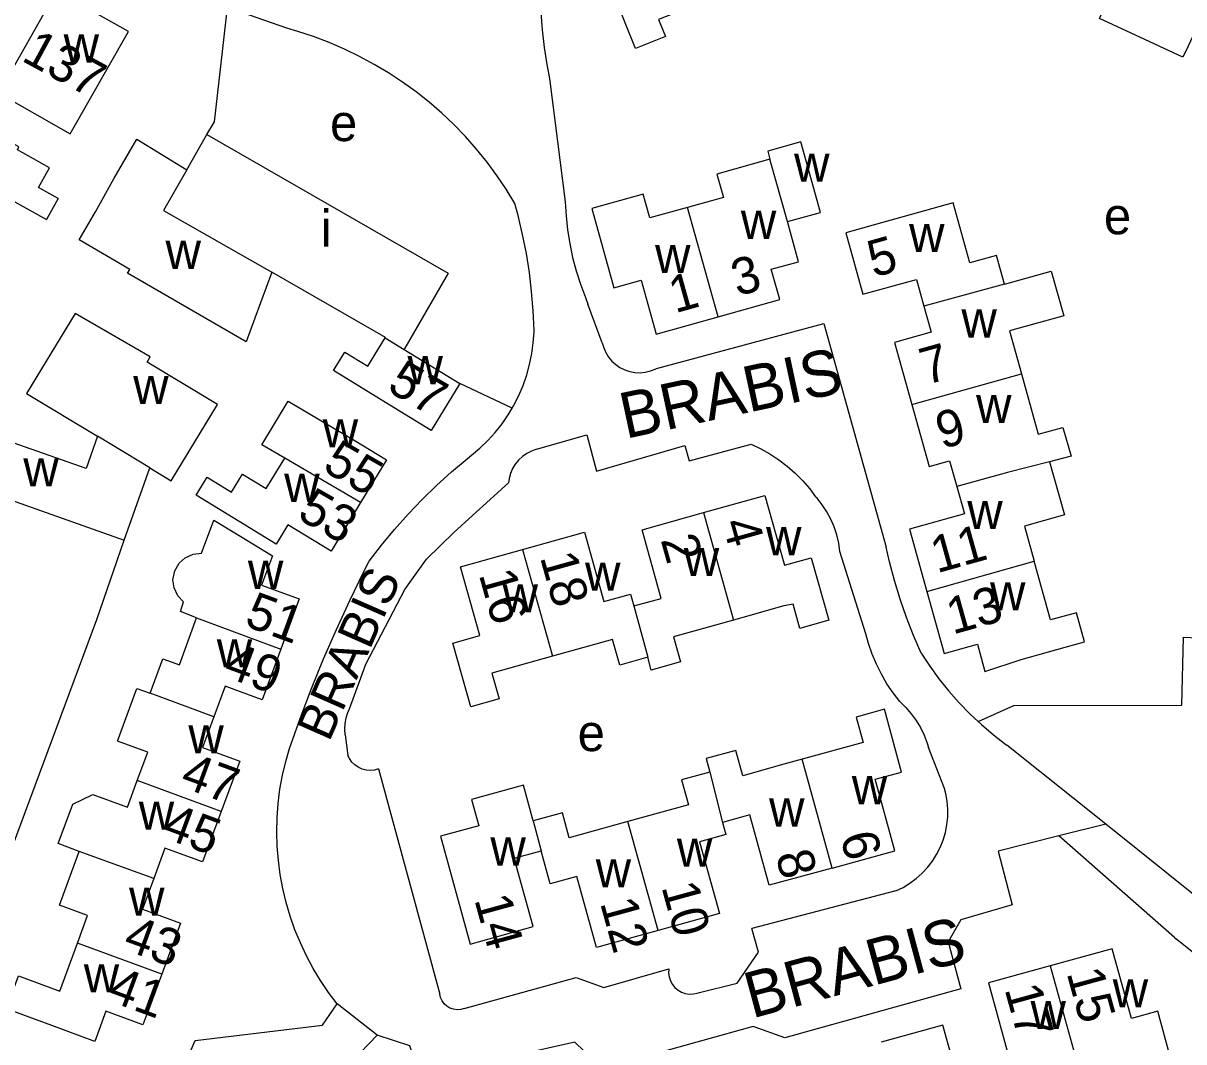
# Model space of a CAD drawing. Extents: x 162883 to 165538, y 383986 to 385172.
# Drawn here: x 164417 to 164543.6, y 384633.2 to 384744.4 of the extents above; entities that cross this region are included whole.
import ezdxf

# ---------------------------------------------------------------- set-up
doc = ezdxf.new("R2010")
doc.units = 0
for name, color, linetype in [('BLT_Basislijn', 7, 'Continuous'), ('BLT_Bebouwing', 7, 'Continuous'), ('BLT_Centroide', 7, 'Continuous'), ('BLT_Huisnummer', 7, 'Continuous'), ('BLT_Huisnummer_ tussenligend', 7, 'Continuous'), ('BLT_Onderverdeling_panden', 7, 'Continuous'), ('BLT_Straatnaam', 7, 'Continuous'), ('BLT_Straatnaam_verkleind', 7, 'Continuous')]:
    doc.layers.add(name, color=color, linetype=linetype)

msp = doc.modelspace()

# ---------------------------------------------------------------- linework, layer by layer
at = {"layer": 'BLT_Basislijn'}
for p, q in [((164445.76, 384743.83), (164439.29, 384746.09)), ((164474.44, 384738.33), (164476.15, 384724.88)), ((164480.19, 384709.5), (164478.6, 384713.69)), ((164470.36, 384702.37), (164464.66, 384705.05)), ((164473.02, 384697.86), (164478.51, 384699.46)), ((164508.96, 384677.72), (164506.12, 384686.72)), ((164452.15, 384666.7), (164452.43, 384664.43)), ((164517.53, 384660.85), (164515.78, 384665.3)), ((164535.12, 384656.94), (164524.34, 384665.57)), ((164455.77, 384662.98), (164462.47, 384638.39)), ((164535.12, 384656.94), (164530.02, 384655.67)), ((164545.44, 384648.68), (164535.12, 384656.94)), ((164542.62, 384644.56), (164530.02, 384655.67)), ((164512.23, 384649.67), (164496.52, 384645.57)), ((164490.78, 384638.57), (164494.89, 384639.58)), ((164455.61, 384633.93), (164451.25, 384637.34))]:
    msp.add_line(p, q, dxfattribs=at)
for points in [[(164437.05, 384732.24), (164437.89, 384733.59), (164439.29, 384746.09)], [(164473.5, 384745.53), (164473.64, 384743.63), (164473.85, 384741.73), (164474.15, 384739.85), (164474.44, 384738.33)], [(164470.66, 384724.69), (164469.71, 384726.24), (164468.69, 384727.75), (164467.61, 384729.22), (164466.46, 384730.63), (164465.26, 384731.99), (164463.99, 384733.3), (164462.67, 384734.55), (164461.29, 384735.75), (164459.87, 384736.88), (164458.39, 384737.95), (164456.87, 384738.95), (164455.31, 384739.88), (164453.7, 384740.75), (164452.07, 384741.54), (164450.39, 384742.26), (164448.69, 384742.91), (164446.96, 384743.48), (164445.76, 384743.83)], [(164472.74, 384710.86), (164472.65, 384712.96), (164472.48, 384715.07), (164472.23, 384717.16), (164471.91, 384719.25), (164471.5, 384721.32), (164471.01, 384723.37), (164470.66, 384724.69)], [(164476.15, 384724.88), (164476.23, 384723.35), (164476.39, 384721.82), (164476.63, 384720.31), (164476.95, 384718.81), (164477.35, 384717.33), (164477.83, 384715.87), (164478.37, 384714.44), (164478.6, 384713.69)], [(164486.09, 384706.68), (164504.36, 384711.61), (164511.18, 384687.17)], [(164470.36, 384702.37), (164470.54, 384702.67), (164471.08, 384703.74), (164471.55, 384704.84), (164471.94, 384705.98), (164472.26, 384707.13), (164472.5, 384708.31), (164472.66, 384709.49), (164472.74, 384710.69), (164472.74, 384710.86)], [(164480.19, 384709.5), (164480.34, 384708.95), (164480.57, 384708.42), (164480.87, 384707.93), (164481.23, 384707.49), (164481.65, 384707.11), (164482.12, 384706.78), (164482.64, 384706.53), (164483.18, 384706.35), (164483.74, 384706.25), (164484.31, 384706.22), (164484.88, 384706.28), (164485.44, 384706.41), (164485.97, 384706.62), (164486.09, 384706.68)], [(164465.93, 384697.21), (164466.84, 384697.99), (164467.7, 384698.82), (164468.51, 384699.71), (164469.25, 384700.65), (164469.93, 384701.64), (164470.36, 384702.37)], [(164478.51, 384699.46), (164479.57, 384695.46), (164489.18, 384698.26), (164489.66, 384696.61), (164496.44, 384698.42)], [(164473.02, 384697.86), (164472.47, 384697.67), (164471.96, 384697.41), (164471.48, 384697.08), (164471.06, 384696.69), (164470.69, 384696.24), (164470.39, 384695.75), (164470.16, 384695.22), (164470.01, 384694.67), (164469.94, 384694.2)], [(164496.44, 384698.42), (164497.49, 384697.93), (164498.49, 384697.36), (164499.46, 384696.72), (164500.38, 384696.02), (164501.25, 384695.25), (164502.06, 384694.43), (164502.82, 384693.55), (164503.47, 384692.69)], [(164454.75, 384685.65), (164456.1, 384687.41), (164457.52, 384689.12), (164458.99, 384690.77), (164460.52, 384692.37), (164462.11, 384693.92), (164463.75, 384695.4), (164465.45, 384696.83), (164465.93, 384697.21)], [(164452.62, 384669.54), (164454.37, 384674.4), (164458.63, 384682.55), (164461, 384685.87), (164464.03, 384688.8), (164469.94, 384694.2)], [(164506.12, 384686.72), (164505.99, 384687.62), (164505.78, 384688.52), (164505.49, 384689.39), (164505.13, 384690.23), (164504.69, 384691.03), (164504.19, 384691.8), (164503.62, 384692.52), (164503.47, 384692.69)], [(164408.67, 384626.64), (164409.63, 384627.68), (164410.94, 384641.5), (164425.03, 384679.28), (164428.03, 384687.96)], [(164514.97, 384675.61), (164514.14, 384677.55), (164513.37, 384679.52), (164512.68, 384681.52), (164512.07, 384683.54), (164511.54, 384685.58), (164511.18, 384687.17)], [(164446.04, 384665.19), (164447.21, 384668.49), (164448.46, 384671.75), (164449.78, 384674.99), (164451.17, 384678.2), (164452.63, 384681.37), (164454.17, 384684.51), (164454.75, 384685.65)], [(164512.65, 384670.33), (164511.92, 384671.28), (164511.24, 384672.28), (164510.64, 384673.32), (164510.1, 384674.4), (164509.64, 384675.51), (164509.25, 384676.65), (164508.96, 384677.72)], [(164521.22, 384668.14), (164525.08, 384669.9), (164543.44, 384669.93), (164543.63, 384677.35), (164554, 384676.9)], [(164514.97, 384675.61), (164515.92, 384674.19), (164516.93, 384672.81), (164518, 384671.48), (164519.13, 384670.2), (164520.32, 384668.97), (164521.22, 384668.14)], [(164512.65, 384670.33), (164513.31, 384669.69), (164513.91, 384669), (164514.44, 384668.26), (164514.91, 384667.48), (164515.31, 384666.66), (164515.63, 384665.8), (164515.78, 384665.3)], [(164452.15, 384666.7), (164452.1, 384667.32), (164452.13, 384667.94), (164452.25, 384668.55), (164452.44, 384669.14), (164452.62, 384669.54)], [(164521.22, 384668.14), (164521.57, 384667.81), (164522.87, 384666.7), (164524.23, 384665.65), (164524.34, 384665.57)], [(164451.25, 384637.34), (164450.31, 384638.58), (164449.44, 384639.87), (164448.64, 384641.2), (164447.9, 384642.58), (164447.24, 384643.99), (164446.65, 384645.43), (164446.14, 384646.9), (164445.7, 384648.39), (164445.33, 384649.91), (164445.05, 384651.44), (164444.85, 384652.98), (164444.72, 384654.54), (164444.68, 384656.09), (164444.71, 384657.65), (164444.83, 384659.2), (164445.02, 384660.75), (164445.3, 384662.28), (164445.65, 384663.8), (164446.04, 384665.19)], [(164455.77, 384662.98), (164455.33, 384662.85), (164454.88, 384662.81), (164454.42, 384662.85), (164453.98, 384662.96), (164453.56, 384663.15), (164453.18, 384663.41), (164452.86, 384663.73), (164452.59, 384664.11), (164452.43, 384664.43)], [(164512.23, 384649.67), (164513.01, 384650.04), (164513.75, 384650.49), (164514.44, 384651), (164515.09, 384651.58), (164515.68, 384652.21), (164516.21, 384652.89), (164516.67, 384653.62), (164517.06, 384654.39), (164517.38, 384655.19), (164517.63, 384656.02), (164517.8, 384656.87), (164517.88, 384657.73), (164517.89, 384658.59), (164517.82, 384659.45), (164517.67, 384660.3), (164517.53, 384660.85)], [(164530.02, 384655.67), (164523.39, 384654.01), (164524.91, 384648.14), (164519.33, 384646.51), (164517.95, 384644.09), (164519.33, 384638.96), (164500.12, 384633.64), (164496.67, 384634.86), (164480.18, 384630.26), (164477.19, 384633.17), (164460.34, 384629.38), (164459.19, 384632.74), (164455.61, 384633.93)], [(164494.89, 384639.58), (164497.22, 384642.99), (164496.52, 384645.57)], [(164542.62, 384644.56), (164543.62, 384643.83), (164544.57, 384643.03), (164545.47, 384642.18), (164546.31, 384641.27), (164547.09, 384640.3), (164547.8, 384639.29), (164548.45, 384638.24), (164549.03, 384637.15), (164549.54, 384636.02), (164549.97, 384634.86), (164550.33, 384633.67), (164550.49, 384633.01)], [(164465.12, 384636.82), (164477.35, 384640.22), (164480.35, 384639.11), (164487.45, 384641.14)], [(164487.45, 384641.14), (164487.43, 384640.7), (164487.49, 384640.27), (164487.63, 384639.85), (164487.84, 384639.46), (164488.12, 384639.12), (164488.46, 384638.84), (164488.84, 384638.62), (164489.25, 384638.47), (164489.69, 384638.4), (164490.13, 384638.41), (164490.56, 384638.5), (164490.78, 384638.57)], [(164465.12, 384636.82), (164464.74, 384636.71), (164464.34, 384636.69), (164463.95, 384636.74), (164463.57, 384636.88), (164463.23, 384637.09), (164462.94, 384637.35), (164462.71, 384637.68), (164462.55, 384638.04), (164462.47, 384638.39)], [(164455.61, 384633.93), (164446.71, 384624.64), (164445.93, 384620.98), (164443.27, 384620.28), (164440.41, 384622.61), (164447.71, 384630.68), (164446.66, 384632.04), (164441.79, 384631.37), (164436.24, 384626.66), (164433.96, 384629.09), (164435.76, 384633.33), (164449.67, 384635.02), (164451.25, 384637.34)]]:
    msp.add_lwpolyline(points, dxfattribs=at)
at = {"layer": 'BLT_Bebouwing'}
for p, q in [((164434.84, 384728.37), (164437.05, 384732.24)), ((164437.05, 384732.24), (164463.36, 384717.08)), ((164426.94, 384727.45), (164429.39, 384731.71)), ((164429.39, 384731.71), (164434.84, 384728.37)), ((164424.87, 384723.78), (164426.94, 384727.45)), ((164420.83, 384725.24), (164419.54, 384722.93)), ((164423.09, 384720.71), (164424.87, 384723.78)), ((164428.62, 384717.5), (164423.09, 384720.71)), ((164428.39, 384717.1), (164428.62, 384717.5)), ((164441.33, 384709.6), (164428.39, 384717.1)), ((164444.12, 384717.19), (164442.28, 384712.18)), ((164442.28, 384712.18), (164441.33, 384709.6)), ((164458.57, 384708.77), (164464.66, 384705.05)), ((164455.88, 384703.38), (164450.86, 384706.45)), ((164445.91, 384703.11), (164453.11, 384698.86)), ((164428.03, 384687.96), (164430.8, 384695.83))]:
    msp.add_line(p, q, dxfattribs=at)
for points in [[(164539.94, 384756.66), (164546.01, 384753.84), (164544.23, 384750), (164545.33, 384752.36), (164548.33, 384750.96), (164544.11, 384741.88), (164543.54, 384740.65), (164539.39, 384742.58), (164534.44, 384744.89), (164535.3, 384746.69)], [(164492.35, 384747.19), (164486.33, 384744.77), (164487.07, 384742.92), (164483.83, 384741.61), (164479.61, 384752.14), (164482.65, 384753.36)], [(164422.14, 384732.28), (164428.49, 384743.45), (164420.65, 384747.89), (164414.32, 384736.72), (164422.14, 384732.28)], [(164413.98, 384732.31), (164409.59, 384734.76), (164406.91, 384729.98), (164411.28, 384727.54), (164419.54, 384722.93)], [(164420.83, 384725.24), (164418.68, 384726.45), (164419.88, 384728.6), (164416.36, 384730.56), (164416.54, 384730.88), (164413.98, 384732.31)], [(164500.4, 384722.71), (164504.01, 384723.71), (164501.86, 384731.41), (164498.25, 384730.4), (164498.49, 384729.53)], [(164498.49, 384729.53), (164492.7, 384727.91), (164493.41, 384725.36), (164489.48, 384724.26)], [(164489.48, 384724.26), (164485.36, 384723.11), (164484.64, 384725.71), (164479.04, 384724.15), (164481.46, 384715.5), (164484.43, 384716.33), (164486.08, 384710.44), (164492.82, 384712.32)], [(164524.07, 384715.87), (164523.19, 384719.03), (164520.31, 384718.23), (164518.49, 384724.76), (164511.56, 384722.83), (164506.75, 384721.48), (164508.62, 384714.78), (164514.46, 384716.41), (164515.28, 384713.47)], [(164492.82, 384712.32), (164499.56, 384714.21), (164498.63, 384717.52), (164501.61, 384718.31), (164500.4, 384722.71)], [(164456.51, 384710.03), (164456.55, 384710.08), (164444.12, 384717.19)], [(164463.36, 384717.08), (164458.64, 384708.89), (164458.57, 384708.77)], [(164524.07, 384715.87), (164529.18, 384717.3), (164530.54, 384712.44), (164524.61, 384710.78), (164525.92, 384706.1)], [(164515.28, 384713.47), (164516.07, 384710.65), (164512.06, 384709.53), (164513.96, 384702.76)], [(164422.67, 384712.67), (164417.37, 384703.94), (164425.1, 384699.28)], [(164438.2, 384702.77), (164430.51, 384707.39), (164430.84, 384707.95), (164422.67, 384712.67)], [(164450.86, 384706.45), (164452.1, 384708.48), (164454.62, 384706.94), (164456.51, 384710.03)], [(164525.92, 384706.1), (164527.76, 384699.5), (164530.46, 384700.25), (164531.34, 384697.11), (164529, 384696.51)], [(164464.66, 384705.05), (164461.52, 384699.93), (164455.88, 384703.38)], [(164430.8, 384695.83), (164433.13, 384694.41), (164438.2, 384702.77)], [(164445.54, 384696.88), (164443.04, 384698.34), (164445.91, 384703.11)], [(164513.96, 384702.76), (164515.85, 384695.99), (164518.08, 384696.61), (164518.87, 384693.8)], [(164414.54, 384699.04), (164409.82, 384700.7), (164407.82, 384694.99), (164404.71, 384696.09), (164403.68, 384693.15), (164403.18, 384693.32), (164402.26, 384690.71), (164402.79, 384690.53), (164402.51, 384689.74), (164407.23, 384688.08), (164410.44, 384686.95), (164412.69, 384693.35), (164428.03, 384687.96)], [(164425.1, 384699.28), (164423.86, 384695.76), (164414.54, 384699.04)], [(164453.11, 384698.86), (164456.64, 384696.72), (164453.82, 384692.07)], [(164453.82, 384692.07), (164450.59, 384686.76), (164445.89, 384689.62), (164444.6, 384687.5), (164435.87, 384692.87), (164437.06, 384694.82), (164439.74, 384693.17), (164440.94, 384695.14), (164443.51, 384693.57), (164445.54, 384696.88)], [(164529, 384696.51), (164530.62, 384690.71), (164526.25, 384689.49), (164527.33, 384685.64)], [(164518.87, 384693.8), (164519.7, 384690.83), (164513.7, 384689.15), (164515.59, 384682.36)], [(164491.24, 384690.95), (164497.94, 384692.83), (164500, 384685.47), (164500.07, 384685.21), (164502.98, 384686.03), (164504.9, 384679.2), (164501.75, 384678.32), (164501.01, 384680.97), (164500, 384680.76), (164494.52, 384679.23)], [(164435.92, 384679.45), (164434.15, 384680.17), (164434.5, 384681.23), (164433.87, 384681.88), (164433.46, 384682.75), (164433.34, 384683.63), (164433.53, 384684.6), (164434, 384685.42), (164434.68, 384686.03), (164435.53, 384686.42), (164436.45, 384686.51), (164437.79, 384690.13), (164439.91, 384688.84), (164444.19, 384686.25), (164443.01, 384683.05), (164447.12, 384681.54), (164445.1, 384676.06)], [(164483.65, 384680.76), (164486.63, 384681.59), (164484.54, 384689.07), (164491.24, 384690.95)], [(164471.48, 384686.92), (164478.24, 384688.82), (164480.36, 384681.24), (164483.28, 384682.06), (164483.65, 384680.76)], [(164474.74, 384675.29), (164468.14, 384673.44), (164468.93, 384670.61), (164465.84, 384669.74), (164463.89, 384676.71), (164466.83, 384677.54), (164464.73, 384685.03), (164471.48, 384686.92)], [(164515.59, 384682.36), (164517.49, 384675.57), (164521.12, 384676.58), (164521.95, 384673.61), (164525.89, 384674.91), (164530.71, 384676.25), (164532.81, 384676.84), (164531.92, 384680.03), (164529.11, 384679.25), (164527.33, 384685.64)], [(164430.85, 384671.23), (164432.24, 384674.99), (164434.04, 384674.33), (164435.92, 384679.45)], [(164494.52, 384679.23), (164487.96, 384677.39), (164488.73, 384674.67), (164485.53, 384673.77), (164485.15, 384675.16)], [(164445.1, 384676.06), (164443.06, 384670.53), (164439.02, 384672.02), (164437.79, 384668.67)], [(164485.15, 384675.16), (164482.09, 384674.3), (164481.3, 384677.12), (164474.74, 384675.29)], [(164429.45, 384661.7), (164430.59, 384664.79), (164427.3, 384666), (164429.41, 384671.75), (164430.85, 384671.23)], [(164437.79, 384668.67), (164436.56, 384665.33), (164440.62, 384663.83), (164438.59, 384658.33)], [(164505.26, 384652.16), (164512.12, 384654.04), (164509.97, 384661.87), (164512.84, 384662.62), (164511, 384669.49), (164507.9, 384668.63), (164508.66, 384665.85), (164502.01, 384664.03)], [(164502.01, 384664.03), (164500, 384663.48), (164495.51, 384662.24), (164494.75, 384664.99), (164491.52, 384664.1), (164491.92, 384662.64)], [(164491.92, 384662.64), (164488.85, 384661.79), (164489.61, 384659.05), (164482.98, 384657.22)], [(164423.12, 384653.97), (164420.81, 384654.82), (164422.4, 384659.14), (164424.58, 384660.19), (164428.38, 384658.79), (164429.45, 384661.7)], [(164472.66, 384657.3), (164471.59, 384661.2), (164465.92, 384659.63), (164466.71, 384656.78), (164462.54, 384655.63), (164465.79, 384643.86), (164472.66, 384645.76), (164470.59, 384653.25), (164473.51, 384654.05)], [(164438.59, 384658.33), (164436.56, 384652.83), (164432.47, 384654.34), (164431.24, 384651)], [(164482.98, 384657.22), (164476.58, 384655.45), (164475.83, 384658.17), (164472.66, 384657.3)], [(164493.32, 384657.12), (164493.68, 384655.81), (164490.8, 384655.01), (164492.97, 384647.18), (164486.27, 384645.33)], [(164505.26, 384652.16), (164498.41, 384650.28), (164496.29, 384657.95), (164493.32, 384657.12)], [(164422.92, 384643.97), (164424.03, 384646.98), (164420.96, 384648.11), (164423.12, 384653.97)], [(164486.27, 384645.33), (164479.57, 384643.48), (164477.42, 384651.25), (164474.51, 384650.44), (164473.51, 384654.05)], [(164431.24, 384651), (164430.01, 384647.66), (164434.16, 384646.13), (164432.12, 384640.58)], [(164432.12, 384640.58), (164430.07, 384635.03), (164426.03, 384636.52), (164424.82, 384633.23), (164420.13, 384634.96), (164415.16, 384636.79), (164416.49, 384640.39), (164420.99, 384638.73), (164422.92, 384643.97)], [(164532.31, 384629.76), (164538.65, 384631.51), (164539.42, 384628.74), (164542.7, 384629.65), (164542.13, 384631.7), (164540.8, 384636.52), (164537.92, 384635.73), (164535.83, 384643.33), (164529.08, 384641.47)], [(164529.08, 384641.47), (164522.34, 384639.61), (164524.46, 384631.91), (164521.53, 384631.11), (164522.32, 384628.24)], [(164522.32, 384628.24), (164519.45, 384627.44), (164517.36, 384635.02), (164510.61, 384633.16)]]:
    msp.add_lwpolyline(points, dxfattribs=at)
at = {"layer": 'BLT_Onderverdeling_panden'}
for p, q in [((164500.4, 384722.71), (164498.49, 384729.53)), ((164492.82, 384712.32), (164489.48, 384724.26)), ((164524.07, 384715.87), (164515.28, 384713.47)), ((164513.96, 384702.76), (164525.92, 384706.1)), ((164430.8, 384695.83), (164425.1, 384699.28)), ((164453.82, 384692.07), (164445.54, 384696.88)), ((164491.24, 384690.95), (164494.52, 384679.23)), ((164471.48, 384686.92), (164474.74, 384675.29)), ((164515.59, 384682.36), (164527.33, 384685.64)), ((164483.65, 384680.76), (164485.15, 384675.16)), ((164435.92, 384679.45), (164445.1, 384676.06)), ((164437.79, 384668.67), (164430.85, 384671.23)), ((164505.26, 384652.16), (164502.01, 384664.03)), ((164491.92, 384662.64), (164493.32, 384657.12)), ((164438.59, 384658.33), (164429.45, 384661.7)), ((164472.66, 384657.3), (164473.51, 384654.05)), ((164486.27, 384645.33), (164482.98, 384657.22)), ((164431.24, 384651), (164423.12, 384653.97)), ((164432.12, 384640.58), (164422.92, 384643.97)), ((164529.08, 384641.47), (164532.31, 384629.76))]:
    msp.add_line(p, q, dxfattribs=at)
for points in [[(164434.84, 384728.37), (164432.3, 384723.94), (164444.12, 384717.19)], [(164456.51, 384710.03), (164458.57, 384708.77)], [(164529, 384696.51), (164524.4, 384695.34), (164518.87, 384693.8)]]:
    msp.add_lwpolyline(points, dxfattribs=at)

# ---------------------------------------------------------------- texts
at = {"layer": 'BLT_Centroide'}
for s, p in [('w', (164421.41, 384740.08)), ('e', (164450.48, 384731.5)), ('w', (164501.12, 384727.06)), ('e', (164534.93, 384721.34)), ('i', (164449.46, 384719.97)), ('w', (164495.31, 384720.83)), ('w', (164513.67, 384719.38)), ('w', (164432.53, 384717.55)), ('w', (164485.95, 384717.09)), ('w', (164519.38, 384710.06)), ('w', (164458.93, 384704.97)), ('w', (164429, 384702.81)), ('w', (164520.98, 384700.72)), ('w', (164449.68, 384698.06)), ('w', (164417.01, 384693.81)), ('w', (164445.48, 384692.12)), ('w', (164520.02, 384689.16)), ('w', (164498.06, 384686.3)), ('w', (164489.08, 384684.03)), ('w', (164441.52, 384682.62)), ('w', (164478.31, 384682.42)), ('w', (164469.31, 384680.05)), ('w', (164522.5, 384680.28)), ('w', (164438.12, 384674.06)), ('w', (164435.02, 384664.67)), ('e', (164477.5, 384664.92)), ('w', (164507.42, 384659.12)), ('w', (164498.39, 384656.69)), ('w', (164429.61, 384656.34)), ('w', (164467.98, 384652.42)), ('w', (164488.33, 384652.3)), ('w', (164479.47, 384650.05)), ('w', (164428.55, 384646.95)), ('w', (164423.61, 384638.59)), ('w', (164535.89, 384636.94)), ('w', (164526.92, 384634.58))]:
    msp.add_text(s, height=4, dxfattribs=at).set_placement(p)
at = {"layer": 'BLT_Huisnummer'}
for s, rotation, p in [('137', 331.4356, (164416.68, 384740.34)), ('5', 15.6184, (164509.8, 384716.6)), ('3', 15.617, (164494.93, 384714.54)), ('1', 15.617, (164488.13, 384712.7)), ('57', 329.5885, (164456.55, 384704.33)), ('9', 15.6176, (164517.26, 384697.87)), ('55', 330.1367, (164449.52, 384695.61)), ('53', 330.1367, (164446.75, 384690.39)), ('4', 285.6556, (164493.25, 384689.82)), ('2', 285.6556, (164486.54, 384688.01)), ('18', 285.6581, (164473.37, 384686.1)), ('16', 285.653, (164466.7, 384684.21)), ('13', 15.6152, (164518.43, 384677.63)), ('51', 339.7633, (164441, 384678.65)), ('45', 339.7713, (164432, 384655.56)), ('6', 285.3412, (164506.12, 384655.6)), ('10', 285.3412, (164486.63, 384650.11)), ('14', 285.3412, (164466.21, 384648.73)), ('41', 339.7541, (164426.06, 384637.75)), ('15', 285.4148, (164530.84, 384640.71))]:
    msp.add_text(s, height=4, rotation=rotation, dxfattribs=at).set_placement(p)
at = {"layer": 'BLT_Huisnummer_ tussenligend'}
for s, rotation, p in [('7', 15.6184, (164515.51, 384704.87)), ('11', 15.6176, (164516.7, 384684.32)), ('49', 339.7633, (164438.69, 384673.15)), ('47', 339.7713, (164433.98, 384661.11)), ('8', 285.3412, (164499.07, 384653.57)), ('12', 285.3412, (164479.93, 384648.37)), ('43', 339.7541, (164427.75, 384643.34)), ('17', 285.4148, (164524.07, 384638.95))]:
    msp.add_text(s, height=4, rotation=rotation, dxfattribs=at).set_placement(p)
at = {"layer": 'BLT_Straatnaam'}
for rotation, p in [(12.1056, (164482.72, 384698.99)), (15.1297, (164496.52, 384635.72))]:
    msp.add_text('BRABIS', height=5, rotation=rotation, dxfattribs=at).set_placement(p)
at = {"layer": 'BLT_Straatnaam_verkleind'}
for s, rotation, p in [('KROMMENBEEMD', 325.6789, (164535.9, 384768.54)), ('BRABIS', 66.2179, (164450.37, 384665.82))]:
    msp.add_text(s, height=4, rotation=rotation, dxfattribs=at).set_placement(p)

doc.saveas('drawing.dxf')
